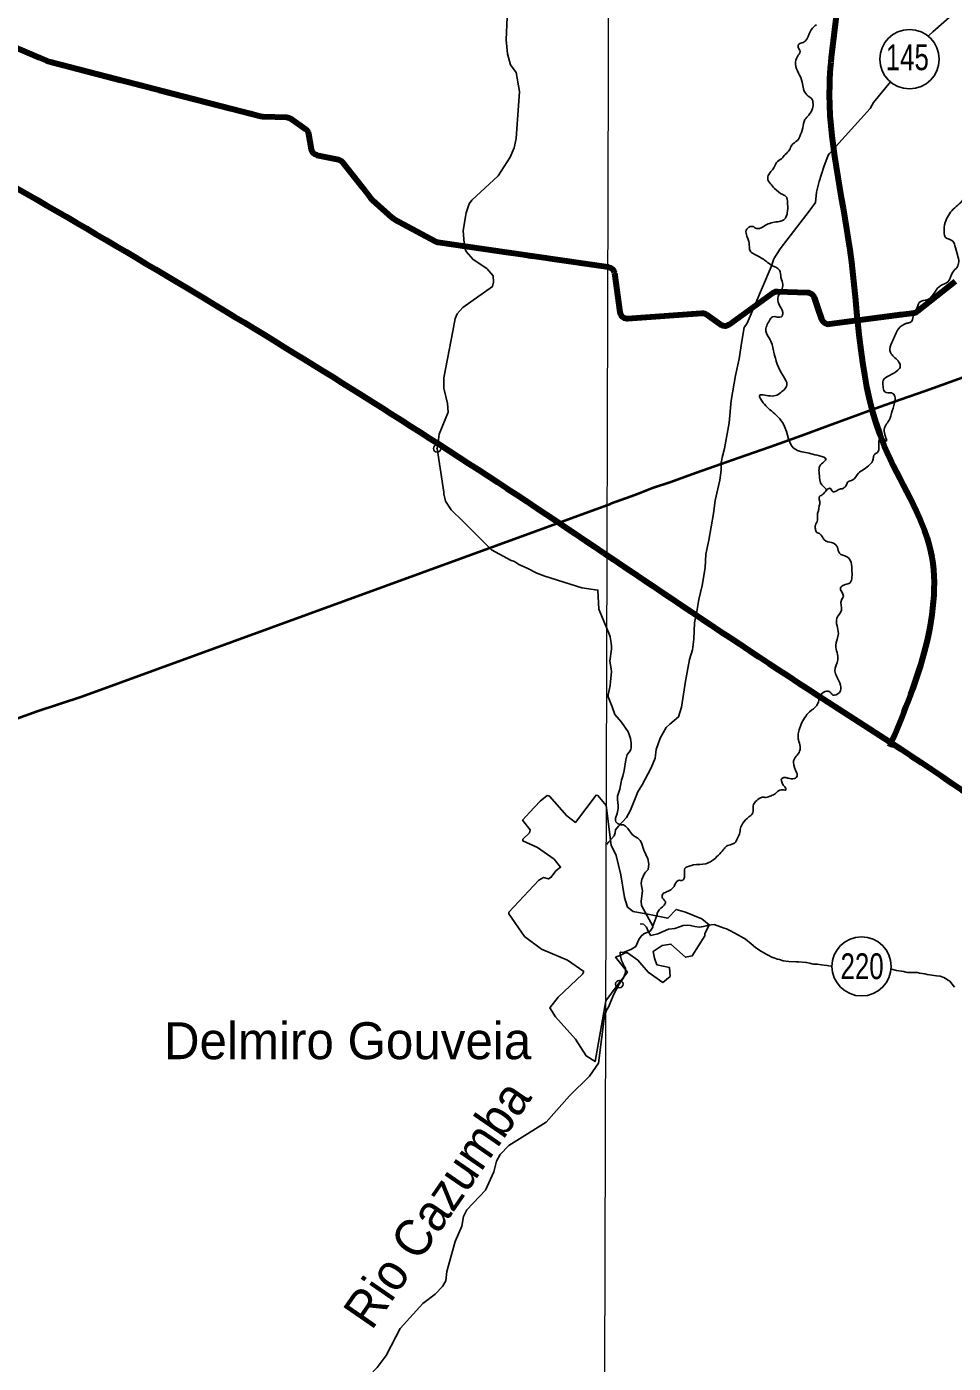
# Model space of a CAD drawing. Extents: x 553962 to 842807, y 8883888 to 9032388.
# Drawn here: x 601949 to 614509, y 8956284 to 8974395 of the extents above; entities that cross this region are included whole.
import ezdxf
from ezdxf.enums import TextEntityAlignment as Align

# ---------------------------------------------------------------- set-up
doc = ezdxf.new("R2010")
doc.units = 0
doc.header["$LTSCALE"] = 200
doc.header["$PDMODE"] = 32
doc.header["$PDSIZE"] = 100
doc.linetypes.add('DOT_DASHED', pattern=[7.7, 5, -1.2, 0.3, -1.2])
for name, color, linetype, lineweight in [('1', 7, 'Continuous', 13), ('12', 7, 'Continuous', 25), ('21', 7, 'Continuous', 25), ('24', 7, 'Continuous', 25), ('48', 7, 'Continuous', 25), ('7', 7, 'Continuous', 90), ('9', 7, 'Continuous', 90)]:
    doc.layers.add(name, color=color, linetype=linetype, lineweight=lineweight)
doc.layers.add('41', color=7, linetype='Continuous')
doc.layers.add('49', color=7, linetype='Continuous')

msp = doc.modelspace()

# ---------------------------------------------------------------- linework, layer by layer
at = {"layer": '1'}
msp.add_lwpolyline([(609971.9, 9023551.8), (609764.7, 8949706.7), (609734.2, 8939404.4)], dxfattribs=at)
at = {"layer": '12'}
for points in [[(614179.1, 8974275.6), (614232, 8974325.6), (614380.4, 8974459), (614591.6, 8974640.6), (614857, 8974834.3), (614998.5, 8974937.7), (615021.7, 8974991.9), (615045, 8975053), (615091.5, 8975110.2), (615204.3, 8975158.4), (615222.8, 8975168.5)], [(612832.5, 8972676.8), (613380.5, 8973289.6), (613425.9, 8973370.8), (613657.1, 8973648.4)], [(612040.3, 8971143.9), (612075.9, 8971248.3), (612161.5, 8971384.7), (612387.3, 8971680.5), (612554.1, 8971895.1), (612640.6, 8972015.5), (612654.9, 8972153.7), (612690.4, 8972298), (612756.6, 8972498.4), (612812.5, 8972654.7), (612832.5, 8972676.8)], [(611360.5, 8968467.9), (611360.9, 8968494.9), (611366.6, 8968506), (611377.4, 8968558.1), (611408, 8968681.3), (611469.3, 8969025.9), (611498.7, 8969332.5), (611555.6, 8969669.1), (611608.8, 8969893.5), (611644.5, 8970132.9), (611675.2, 8970318.3), (611717, 8970376.4), (612040.3, 8971143.9)], [(610973, 8965953.3), (610994.3, 8966098.6), (611002.5, 8966316), (611033.2, 8966472.2), (611059.2, 8966633.6), (611105, 8966822.9), (611145.7, 8967062.3), (611155.3, 8967247.7), (611194.3, 8967437), (611259.2, 8967798.7), (611279.7, 8967975), (611318.7, 8968135.3), (611346, 8968249.5), (611361.8, 8968386.8), (611360.5, 8968467.9)], [(609806.8, 8963316.2), (609840.1, 8963350.5), (609910.5, 8963433.7), (609927.6, 8963470.8), (609929.6, 8963512.9), (609970.7, 8963564), (610080.1, 8963678.4), (610134.1, 8963777.6), (610234.6, 8964027.2), (610293.4, 8964122.4), (610411.7, 8964351), (610469.1, 8964484.3), (610483.5, 8964599.5), (610535.5, 8964754.8), (610616.8, 8964899.1), (610667.4, 8964945.3), (610786.4, 8965043.6), (610825.3, 8965173.9), (610880.8, 8965525.5), (610933.4, 8965820.1), (610973, 8965953.3)], [(610264.1, 8962237.4), (610311.1, 8962234.5), (610316, 8962231.5), (610349.4, 8962192.5), (610374.6, 8962139.5), (610404.7, 8962083.4), (610408.2, 8962079.4), (610506.1, 8962105.6), (610649.1, 8962166.9), (610736.5, 8962174.1), (610812.1, 8962204.2), (610848.7, 8962215.3), (610911.8, 8962219.4), (610943.7, 8962217.5), (611006.1, 8962203.6), (611065.8, 8962194.6), (611093.8, 8962196.7), (611122.5, 8962202.7), (611157.7, 8962212.8), (611189.8, 8962219.9), (611269.6, 8962231), (611402.6, 8962182.1), (611435.5, 8962173.2), (611490.1, 8962144.2), (611638.5, 8962063.3), (611691.1, 8962029.4), (611771.1, 8961966.4), (611829.3, 8961918.4), (611889.1, 8961876.4), (611971.1, 8961828.5), (611997.8, 8961813.5), (612050.6, 8961788.6), (612077, 8961777.6), (612125.6, 8961761.6), (612153.7, 8961756.7), (612204.9, 8961738.7), (612281.6, 8961727.8), (612380.1, 8961723), (612410.5, 8961723), (612515.1, 8961715.2), (612566.3, 8961705.2), (612591.9, 8961698.3), (612616.6, 8961694.3), (612643, 8961692.3), (612669.5, 8961691.4), (612719.8, 8961683.5), (612795.6, 8961675.6), (612823.8, 8961668.6), (612864.6, 8961663.8)], [(613672.1, 8961625.4), (613738.4, 8961606.9), (613840.6, 8961591.1), (613866.3, 8961585.1), (613888.9, 8961581.1), (613942.1, 8961579.2), (613971.7, 8961581.3), (614023.1, 8961578.3), (614049.5, 8961572.4), (614124.5, 8961561.5), (614153.6, 8961554.5), (614252.3, 8961537.6), (614280.5, 8961536.7), (614332.5, 8961530.8), (614382, 8961510.8), (614463.3, 8961460.9), (614523.8, 8961379.8)]]:
    msp.add_lwpolyline(points, dxfattribs=at)
at = {"layer": '12', "lineweight": 40}
for points in [[(616723.1, 8970254.2), (616475.2, 8970206.7), (616247.5, 8970158.2), (616024, 8970116.8), (615816.8, 8970075.4), (615681.8, 8970025.2), (615145.1, 8969827), (614804, 8969702.3), (614465.5, 8969579.5), (614127, 8969456.8), (613790, 8969340.1), (613461.1, 8969222.4), (613140.4, 8969103.7), (612819.7, 8968986), (612449.8, 8968852.2), (612021.1, 8968699.3), (611592.4, 8968549.4), (611360.5, 8968467.9)], [(611360.5, 8968467.9), (611013.3, 8968346.2), (610681, 8968223.4), (610434.1, 8968141.9), (610250.3, 8968070.5), (610141.5, 8968028.3), (609861, 8967928.7)], [(593118.3, 8961975.5), (594700.8, 8962547.5), (600985.5, 8964722.4), (602091.6, 8965119.9), (602697.1, 8965318.9), (609861, 8967928.7)]]:
    msp.add_lwpolyline(points, dxfattribs=at)
at = {"layer": '21'}
for points in [[(609804.3, 8963841.6), (609692.8, 8963976.2), (609666.6, 8963982.7), (609387.8, 8963613.5), (609268.7, 8963704.3), (609037.7, 8963969.7), (609005.2, 8963976.3), (608907.9, 8963902.9), (608765.2, 8963749.4), (608768.4, 8963752.9)], [(608768.4, 8963752.9), (608671.8, 8963644.5), (608771.6, 8963513.5), (608763, 8963472.8), (608674.7, 8963384.3), (608674.6, 8963362.6), (608871.1, 8963271.6), (609098.6, 8963116.9), (609185.2, 8963006.2), (609122.6, 8962955.4), (609059.5, 8962870.7), (609020.3, 8962848.1), (608953.3, 8962867.3), (608890.2, 8962830.9), (608482.3, 8962396.3), (608482.2, 8962374.6), (608698.7, 8962069.7), (608927.4, 8961894.7), (609281.9, 8961745.5), (609500, 8961592.1), (609485, 8961557.5), (609154.4, 8961246.1), (609040.8, 8961101.4), (609119, 8960979.5), (609387.8, 8960677.5), (609534.3, 8960449.1), (609653.8, 8960372.8), (609800.8, 8961196.1)], [(609800.8, 8961196.1), (609951.3, 8961405.5), (610091.2, 8961585.5), (609931.3, 8961785.4), (610001.3, 8961815.4), (610061.2, 8961845.4), (610091.2, 8961845.4), (610231.1, 8961745.4), (610371.1, 8961585.5), (610570.9, 8961445.5), (610670.8, 8961525.5), (610660.9, 8961645.5), (610491, 8961685.5), (610461, 8961775.4), (610441, 8961865.4), (610560.9, 8961945.4), (610680.8, 8961965.4), (610880.7, 8961785.4), (610970.7, 8961805.4), (611140.5, 8962075.3), (611140.5, 8962105.3), (611200.5, 8962225.3), (611100.6, 8962305.2), (610880.7, 8962395.2), (610750.8, 8962435.2), (610640.9, 8962315.2), (610391, 8962365.2), (610171.2, 8962405.2), (610091.2, 8962465.2), (610051.2, 8962595.2), (610001.3, 8962905.1), (609941.3, 8963165), (609871.4, 8963304.9), (609804.3, 8963841.6)]]:
    msp.add_lwpolyline(points, dxfattribs=at)
at = {"layer": '24'}
msp.add_line((607511.6, 8968680.9), (607530.5, 8968802.4), dxfattribs=at)
for points in [[(607981.4, 8972045.9), (608340.3, 8972373.2), (608504, 8972626.3), (608557, 8972753.5), (608584.6, 8972880.9), (608629.2, 8973517.9), (608582.5, 8973773.1), (608506, 8973879.6), (608465.7, 8974028), (608448.7, 8974219.2), (608463.5, 8974525.1), (608412.1, 8974909.8)], [(608277, 8970937.8), (608271.1, 8971022.2), (608185.2, 8971119.9), (608000.5, 8971241), (607905, 8971351.2), (607881.9, 8971405.8), (607866.6, 8971636.1), (607904.8, 8971873.7), (607947.8, 8971995.4), (607981.4, 8972045.9)], [(607724.4, 8970268.8), (607758.4, 8970442.5), (607781.8, 8970504.1), (607860.2, 8970591), (608262.7, 8970873.9), (608277.1, 8970936.2), (608277, 8970937.8)], [(607530.5, 8968802.4), (607541.7, 8968874.6), (607660.5, 8969172.2), (607652.1, 8969290.7), (607601.1, 8969498.9), (607601.1, 8969639.1), (607724.4, 8970268.8)], [(607703.2, 8967850.5), (607627.7, 8967964.3), (607614.9, 8968008), (607605.5, 8968061.2), (607601.1, 8968086.8), (607511.6, 8968680.9)], [(608515.8, 8967162.6), (608251.1, 8967306.9), (607860.2, 8967694.8), (607703.2, 8967850.5)], [(609474.2, 8966790.4), (608973.4, 8966950.1), (608864.6, 8966990.5), (608731.8, 8967057), (608620.3, 8967109.1), (608563.4, 8967149.5), (608515.8, 8967162.6)], [(609841.5, 8966176.9), (609704.1, 8966503.7), (609693, 8966762.7), (609474.2, 8966790.4)], [(610371.4, 8962976.2), (610379.8, 8963013.8), (610382.1, 8963047.9), (610367.5, 8963120), (610314.8, 8963239.1), (610282.3, 8963338.2), (610265.4, 8963370.2), (610232.8, 8963402.2), (610193.3, 8963421.2), (610157.8, 8963448.2), (610095.6, 8963532.2), (610066.7, 8963561.2), (610036.6, 8963580.2), (610003.6, 8963581.1), (609956.2, 8963599.1), (609936, 8963623.1), (609928.6, 8963640.1), (609929.5, 8963669.1), (609954.4, 8963735.3), (609968.3, 8963800.4), (609967.7, 8963842.5), (609955.3, 8963923.6), (609957.6, 8963969.7), (609987.3, 8964065.8), (610009.7, 8964184.1), (610029.9, 8964242.2), (610049.4, 8964318.3), (610070.6, 8964459.6), (610090.6, 8964534.7), (610118.8, 8964569.8), (610136.5, 8964599.9), (610143.2, 8964627), (610143.3, 8964686.1), (610132.5, 8964751.1), (610117.5, 8964805.2), (610101.9, 8964839.2), (610009.9, 8964971.3), (609920.5, 8965076.3), (609887.1, 8965177.4), (609832.3, 8965315.6), (609830, 8965343.6), (609859.8, 8965469.8), (609861.1, 8965523.9), (609875.2, 8965654.1), (609872.3, 8965696.2), (609853, 8965796.3), (609874, 8965961.6), (609874.8, 8965999.7), (609869.2, 8966072.8), (609858.8, 8966126.9), (609841.5, 8966176.9)], [(609982.1, 8961422.7), (610037.1, 8961507.9), (610064.5, 8961578.1), (610064.2, 8961638.2), (610040.6, 8961677.2), (610038.1, 8961690.2), (610013.3, 8961743.3), (609992.6, 8961823.3), (609993.5, 8961853.4), (609997.6, 8961856.4), (610025.7, 8961851.5), (610048.1, 8961855.5), (610148.5, 8961896.7), (610207.6, 8961933.9), (610245.1, 8962026.1), (610277.6, 8962073.2), (610312.8, 8962103.3), (610398.6, 8962138.5), (610419.5, 8962164.6), (610435.7, 8962195.6), (610437.2, 8962206.7), (610284.5, 8962485.8), (610279.8, 8962547.9), (610295.5, 8962684.2), (610281.3, 8962752.3), (610279.8, 8962791.3), (610289, 8962838.4), (610320, 8962910.6), (610338.8, 8962938.6), (610371.4, 8962976.2)], [(606950.7, 8956641.4), (607010.7, 8956757.8), (607320.7, 8957095.6), (607486.4, 8957220.9), (607586.3, 8957325.3), (607630.8, 8957401.7), (607645.7, 8957526.8), (607756.7, 8957933.8), (607847.4, 8958140.8), (607868.9, 8958272.7), (607915.5, 8958363.8), (608166.1, 8958629.3), (608279.8, 8958879.3), (608317, 8959022.3), (608365.8, 8959111.5), (608484.8, 8959236.8), (608990.2, 8959553.2), (609306.9, 8959910.2), (609576.6, 8960175.8), (609697.7, 8960350), (609780.5, 8960992), (609809.8, 8961070.9), (609834, 8961110), (609904.8, 8961278.4), (609982.1, 8961422.7)], [(606039.3, 8955103.8), (605929.6, 8955224.5), (605999.4, 8955353.7), (606180, 8955619.3), (606269.2, 8955840.2), (606360.2, 8955926.9), (606411.5, 8955999.5), (606589.9, 8956112.1), (606699.8, 8956226.1), (606821.6, 8956390.6), (606950.7, 8956641.4)]]:
    msp.add_lwpolyline(points, dxfattribs=at)
for points in [[(612667.9, 8967747.4), (612667.9, 8967790.6), (612680.2, 8967833.7), (612689.4, 8967892.3), (612701.8, 8967938.6), (612692.5, 8967987.9), (612692.5, 8968024.9), (612726.4, 8968049.6), (612775.7, 8968098.9), (612785, 8968114.3), (612741.8, 8968172.9), (612704.8, 8968231.5), (612692.5, 8968339.4), (612692.5, 8968425.8), (612738.8, 8968487.5), (612781.9, 8968533.7), (612694.2, 8968580), (612482.9, 8968630.8), (612373, 8968664.6), (612212.4, 8969002.9), (612043.3, 8969189), (611899.7, 8969349.7), (611882.8, 8969392), (612026.5, 8969392), (612187.1, 8969451.2), (612254.7, 8969544.2), (612204, 8969662.7), (612077.2, 8969984.1), (612026.5, 8970153.2), (611967.3, 8970271.6), (612018, 8970415.4), (612059.6, 8970464.8), (612178.6, 8970464.8), (612198.5, 8970524.3), (612143.9, 8970638.6), (612134, 8970737.9), (612183.6, 8970832.2), (612198.5, 8970901.7), (612173.7, 8970996.1), (612153.8, 8971095.4), (612034.7, 8971169.8), (611950.4, 8971234.4), (611811.4, 8971313.8), (611756.8, 8971358.5), (611742, 8971462.8), (611712.2, 8971557.2), (611702.3, 8971636.6), (611756.8, 8971686.2), (611801.5, 8971686.2), (611829.2, 8971666.8), (611881.3, 8971661.6), (611964.6, 8971705.9), (612040.2, 8971737.1), (612128.7, 8971752.8), (612212, 8971778.8), (612238.1, 8971812.7), (612258.9, 8971872.6), (612264.1, 8971989.9), (612258.9, 8972052.5), (612245.9, 8972091.6), (612199, 8972120.2), (612087, 8972203.6), (612029.7, 8972268.8), (611993.3, 8972341.7), (612000.3, 8972381.2), (612077.3, 8972484.1), (612113.3, 8972556.1), (612180.2, 8972607.5), (612231.6, 8972664.1), (612288.1, 8972725.8), (612318.9, 8972792.7), (612396, 8972854.4), (612426.9, 8972905.8), (612468, 8973024.1), (612498.8, 8973137.3), (612550.2, 8973199), (612601.6, 8973286.4), (612606.8, 8973368.7), (612596.5, 8973409.9), (612524.5, 8973471.6), (612478.3, 8973553.9), (612462.8, 8973646.5), (612370.3, 8973888.2), (612396, 8973991.1), (612432, 8974057.9), (612406.3, 8974140.2), (612416.6, 8974160.8), (612473.1, 8974181.4), (612555.4, 8974299.7), (612622.2, 8974397.4), (612653, 8974423.1)], [(612786.7, 8968107.3), (612801.6, 8968128.4), (612825.4, 8968137.6), (612841.8, 8968141.2), (612849.1, 8968135.7), (612863.8, 8968104.6), (612885.7, 8968091.8), (612907.7, 8968095.5), (612936.9, 8968110.1), (612958.9, 8968126.6), (613002.8, 8968135.7), (613019.2, 8968144.9), (613052.1, 8968168.7), (613075.9, 8968223.6), (613149.1, 8968256.5), (613222.2, 8968346.2), (613291.7, 8968393.7), (613379.5, 8968463.3), (613410.6, 8968499.9), (613419.7, 8968521.8), (613428.9, 8968573.1), (613434.3, 8968587.7), (613492.9, 8968642.6), (613500.2, 8968675.6), (613500.2, 8968774.4), (613520.8, 8968819.7), (613563.5, 8968810.2), (613601.5, 8968781.7), (613573, 8968914.7), (613639.4, 8969062), (613682.2, 8969190.2), (613720.1, 8969337.5), (613710.7, 8969399.2), (613677.4, 8969432.5), (613601.5, 8969437.2), (613577.7, 8969451.5), (613558.7, 8969522.8), (613558.7, 8969603.5), (613644.2, 8969670), (613758.1, 8969741.3), (613791.3, 8969793.5), (613772.4, 8969850.5), (613667.9, 8969964.5), (613648.9, 8970026.3), (613691.7, 8970145), (613767.6, 8970301.8), (613881.6, 8970377.8), (613929, 8970392), (613962.2, 8970444.3), (613976.5, 8970529.8), (614009.7, 8970567.8), (614047.7, 8970658), (614166.4, 8970700.8), (614261.3, 8970800.5), (614342, 8970890.8), (614437, 8970938.3), (614503.4, 8971071.3), (614560.4, 8971137.8), (614584.1, 8971209.1), (614565.1, 8971304.1), (614531.9, 8971432.3), (614503.4, 8971489.3), (614403.7, 8971541.6), (614384.7, 8971608.1), (614399, 8971741.1), (614508.2, 8971921.6), (614660.1, 8972083.1), (614712.3, 8972154.3), (614750.3, 8972154.3), (614793, 8972097.3), (614854.7, 8972064.1), (614873.7, 8972111.6), (614816.7, 8972387.1), (614812, 8972505.8), (614840.4, 8972594.7), (614887.9, 8972703.9), (614973.4, 8972751.4), (615039.8, 8972760.9), (615187, 8972836.9), (615272.4, 8972998.4), (615315.2, 8973159.9), (615348.4, 8973316.7)], [(610437.2, 8962206.7), (610489.2, 8962352.5), (610507, 8962405.6), (610591.1, 8962494.2), (610608.8, 8962534.1), (610569, 8962587.3), (610569, 8962636), (610622.1, 8962671.5), (610723.9, 8962746.8), (610781.5, 8962826.6), (610843.5, 8962831), (610865.6, 8962932.9), (610878.9, 8962999.4), (610927.6, 8963021.5), (610989.6, 8963039.3), (611153.5, 8963052.6), (611237.6, 8963092.4), (611326.2, 8963170.3), (611391.1, 8963243.8), (611437.2, 8963291.6), (611507.3, 8963317.3), (611551.7, 8963341.2), (611579, 8963390.8), (611611.5, 8963460.9), (611625.2, 8963534.4), (611655.9, 8963601), (611737.9, 8963688.2), (611785.7, 8963732.7), (611797.7, 8963804.5), (611808, 8963871.1), (611830.2, 8963895.1), (611896.8, 8963948.1), (611919, 8963954.9), (611970.2, 8963951.5), (612038.6, 8963975.4), (612098.4, 8964004.5), (612127.4, 8964033.5), (612190.6, 8964055.8), (612224.8, 8964050.6), (612238.5, 8964052.3), (612240.2, 8964069.4), (612206, 8964115.6), (612185.5, 8964161.7), (612177, 8964187.4), (612183.8, 8964207.9), (612226.5, 8964221.6), (612276, 8964211.3), (612310.2, 8964206.2), (612354.6, 8964207.9), (612385.4, 8964225), (612393.9, 8964254), (612385.4, 8964289.9), (612343.5, 8964423.3), (612364, 8964491.7), (612418.7, 8964560.1), (612432.3, 8964642.1), (612411.8, 8964731), (612405, 8964792.5), (612418.7, 8964867.8), (612514.3, 8965059.2), (612562.2, 8965113.9), (612657.8, 8965196), (612753.5, 8965380.6), (612828.7, 8965387.4), (612876.5, 8965339.6), (612965.4, 8965373.7), (612931.2, 8965585.7), (612903.9, 8965667.8), (612944.9, 8965818.2), (612917.5, 8966009.7), (612951.7, 8966173.8), (612931.2, 8966378.9), (612992.7, 8966488.3), (612992.7, 8966625.1), (613020, 8966679.8), (612979, 8966789.2), (613026.9, 8966830.2), (613095.2, 8966850.7), (613136.2, 8967014.8), (613067.9, 8967213.1), (612965.4, 8967261), (612938, 8967343), (612883.4, 8967397.7), (612787.7, 8967425.1), (612753.5, 8967452.4), (612705.7, 8967520.8), (612658.6, 8967543.9), (612640.1, 8967590.1), (612640.1, 8967642.6), (612667.9, 8967707.3), (612667.9, 8967747.4)]]:
    msp.add_spline(points, degree=3, dxfattribs=at)
for p in [(607511.6, 8968680.9), (609982.1, 8961422.7)]:
    msp.add_point(p, dxfattribs=at)
at = {"layer": '48'}
for centre in [(613915.8, 8973955.5), (613266.4, 8961662.9)]:
    msp.add_circle(centre, 401.3, dxfattribs=at)
at = {"layer": '7'}
for points in [[(601203.7, 8974367.8), (602215.4, 8973935.8), (602246, 8973924.9), (602253.1, 8973923), (605119.1, 8973183), (605145.3, 8973178.3), (605158.5, 8973177.4), (605468.7, 8973168.8), (605488.5, 8973166.2), (605507.4, 8973159.8), (605522.8, 8973151.1), (605727.3, 8973009.6), (605742.5, 8972996.7), (605754.8, 8972981), (605763.8, 8972963.1), (605768.9, 8972945), (605805.9, 8972737.1), (605811.4, 8972717.9), (605820.6, 8972700.2), (605833.1, 8972684.6), (605848.4, 8972671.8), (605866, 8972662.4), (605883.5, 8972656.9), (606173.4, 8972595.1), (606192.4, 8972589), (606209.8, 8972579.3), (606225, 8972566.3), (606231.4, 8972558.9), (606500, 8972214.8), (606604.7, 8972080.7), (606624.8, 8972058.2), (606631.9, 8972051.5), (606899.8, 8971811), (606920.4, 8971795.2), (606932.2, 8971788.1), (607485.3, 8971487.7), (607504.8, 8971479.4), (607522.7, 8971475.3), (609830.3, 8971139.9), (609849.7, 8971135.1), (609867.7, 8971126.5), (609883.7, 8971114.5), (609897, 8971099.5), (609907, 8971082.2), (609913.4, 8971063.3), (609915, 8971054.7), (609988, 8970528.8), (609992.7, 8970509.4), (610001.2, 8970491.3), (610013.1, 8970475.3), (610027.9, 8970461.9), (610045.1, 8970451.8), (610064, 8970445.3), (610083.8, 8970442.7), (610094.1, 8970442.8), (611100.1, 8970514)], [(611100.1, 8970514), (611120.1, 8970513.4), (611139.5, 8970508.9), (611157.7, 8970500.6), (611165.2, 8970495.7), (611354.4, 8970360.9), (611371.7, 8970351), (611390.7, 8970344.8), (611410.5, 8970342.4), (611430.5, 8970344), (611449.6, 8970349.6), (611467.3, 8970358.8), (611470.9, 8970361.3), (612064.4, 8970789.5), (612081.7, 8970799.5), (612100.6, 8970805.9), (612120.4, 8970808.4), (612126.3, 8970808.4), (612532.2, 8970794.6), (612552, 8970791.9), (612570.8, 8970785.4), (612588, 8970775.2), (612602.9, 8970761.8), (612614.8, 8970745.8), (612623.2, 8970727.7), (612623.4, 8970727.1), (612675.3, 8970575.8), (612723.8, 8970434.6), (612732.1, 8970416.4), (612743.9, 8970400.3), (612758.6, 8970386.8), (612775.8, 8970376.6), (612794.6, 8970369.9), (612814.4, 8970367.1), (612831.5, 8970367.9), (613977.2, 8970519.4), (613996.6, 8970524), (614014.8, 8970532.3), (614026.1, 8970540.1), (614541.4, 8970947.2)]]:
    msp.add_lwpolyline(points, dxfattribs=at)
at = {"layer": '7', "linetype": 'DOT_DASHED'}
for points in [[(601203.7, 8974367.8), (602215.4, 8973935.8), (602246, 8973924.9), (602253.1, 8973923), (605119.1, 8973183), (605145.3, 8973178.3), (605158.5, 8973177.4), (605468.7, 8973168.8), (605488.5, 8973166.2), (605507.4, 8973159.8), (605522.8, 8973151.1), (605727.3, 8973009.6), (605742.5, 8972996.7), (605754.8, 8972981), (605763.8, 8972963.1), (605768.9, 8972945), (605805.9, 8972737.1), (605811.4, 8972717.9), (605820.6, 8972700.2), (605833.1, 8972684.6), (605848.4, 8972671.8), (605866, 8972662.4), (605883.5, 8972656.9), (606173.4, 8972595.1), (606192.4, 8972589), (606209.8, 8972579.3), (606225, 8972566.3), (606231.4, 8972558.9), (606500, 8972214.8), (606604.7, 8972080.7), (606624.8, 8972058.2), (606631.9, 8972051.5), (606899.8, 8971811), (606920.4, 8971795.2), (606932.2, 8971788.1), (607485.3, 8971487.7), (607504.8, 8971479.4), (607522.7, 8971475.3), (609830.3, 8971139.9), (609849.7, 8971135.1), (609867.7, 8971126.5), (609883.7, 8971114.5), (609897, 8971099.5), (609907, 8971082.2), (609913.4, 8971063.3), (609915, 8971054.7), (609988, 8970528.8), (609992.7, 8970509.4), (610001.2, 8970491.3), (610013.1, 8970475.3), (610027.9, 8970461.9), (610045.1, 8970451.8), (610064, 8970445.3), (610083.8, 8970442.7), (610094.1, 8970442.8), (611100.1, 8970514)], [(611100.1, 8970514), (611120.1, 8970513.4), (611139.5, 8970508.9), (611157.7, 8970500.6), (611165.2, 8970495.7), (611354.4, 8970360.9), (611371.7, 8970351), (611390.7, 8970344.8), (611410.5, 8970342.4), (611430.5, 8970344), (611449.6, 8970349.6), (611467.3, 8970358.8), (611470.9, 8970361.3), (612064.4, 8970789.5), (612081.7, 8970799.5), (612100.6, 8970805.9), (612120.4, 8970808.4), (612126.3, 8970808.4), (612532.2, 8970794.6), (612552, 8970791.9), (612570.8, 8970785.4), (612588, 8970775.2), (612602.9, 8970761.8), (612614.8, 8970745.8), (612623.2, 8970727.7), (612623.4, 8970727.1), (612675.3, 8970575.8), (612723.8, 8970434.6), (612732.1, 8970416.4), (612743.9, 8970400.3), (612758.6, 8970386.8), (612775.8, 8970376.6), (612794.6, 8970369.9), (612814.4, 8970367.1), (612831.5, 8970367.9), (613977.2, 8970519.4), (613996.6, 8970524), (614014.8, 8970532.3), (614026.1, 8970540.1), (614541.4, 8970947.2)]]:
    msp.add_lwpolyline(points, dxfattribs=at)
at = {"layer": '9'}
for points in [[(607019.9, 8987628.8), (608117.9, 8987072.5), (609319, 8986220.3), (609831, 8985717.6), (610444.6, 8985240.9), (611083, 8984865.7), (611314.6, 8984437), (611367.4, 8984108.2), (611371.5, 8983424.7), (611351.3, 8982538.5), (611228.8, 8981727.5), (611158.3, 8980739.6), (611137.7, 8979929.4), (611547.1, 8979552.5), (611828.5, 8979301.3), (612340.6, 8978773.3), (612648.8, 8978294.5), (612832.8, 8977308.5), (612940.5, 8976321.9), (612949.5, 8974803), (612829.3, 8973612.2), (613105.4, 8971372.7), (613572.8, 8968712.3), (614200.8, 8967292.3), (614110, 8965907), (613645.9, 8964639.4)], [(592698.5, 8977198.4), (599903.5, 8973292.7), (608459.2, 8968138.2), (612674.8, 8965332.6), (616842, 8962096.4), (620005, 8958671.2), (621134, 8957974.7), (621473.4, 8956805.3), (621586.2, 8956597.5)]]:
    msp.add_spline(points, degree=3, dxfattribs=at)

# ---------------------------------------------------------------- texts
at = {"layer": '41'}
msp.add_text('Delmiro Gouveia', height=500, dxfattribs=at).set_placement((603808.9, 8960405.2))
at = {"layer": '48', "width": 0.75}
for s, p in [('145', (613885.7, 8973806.7)), ('220', (613273, 8961489.6))]:
    msp.add_text(s, height=350, dxfattribs=at).set_placement(p, align=Align.CENTER)
at = {"layer": '49', "width": 0.95}
msp.add_text('Rio Cazumba', height=500, rotation=55.429, dxfattribs=at).set_placement((607716.8, 8958303), align=Align.CENTER)

doc.saveas('drawing.dxf')
